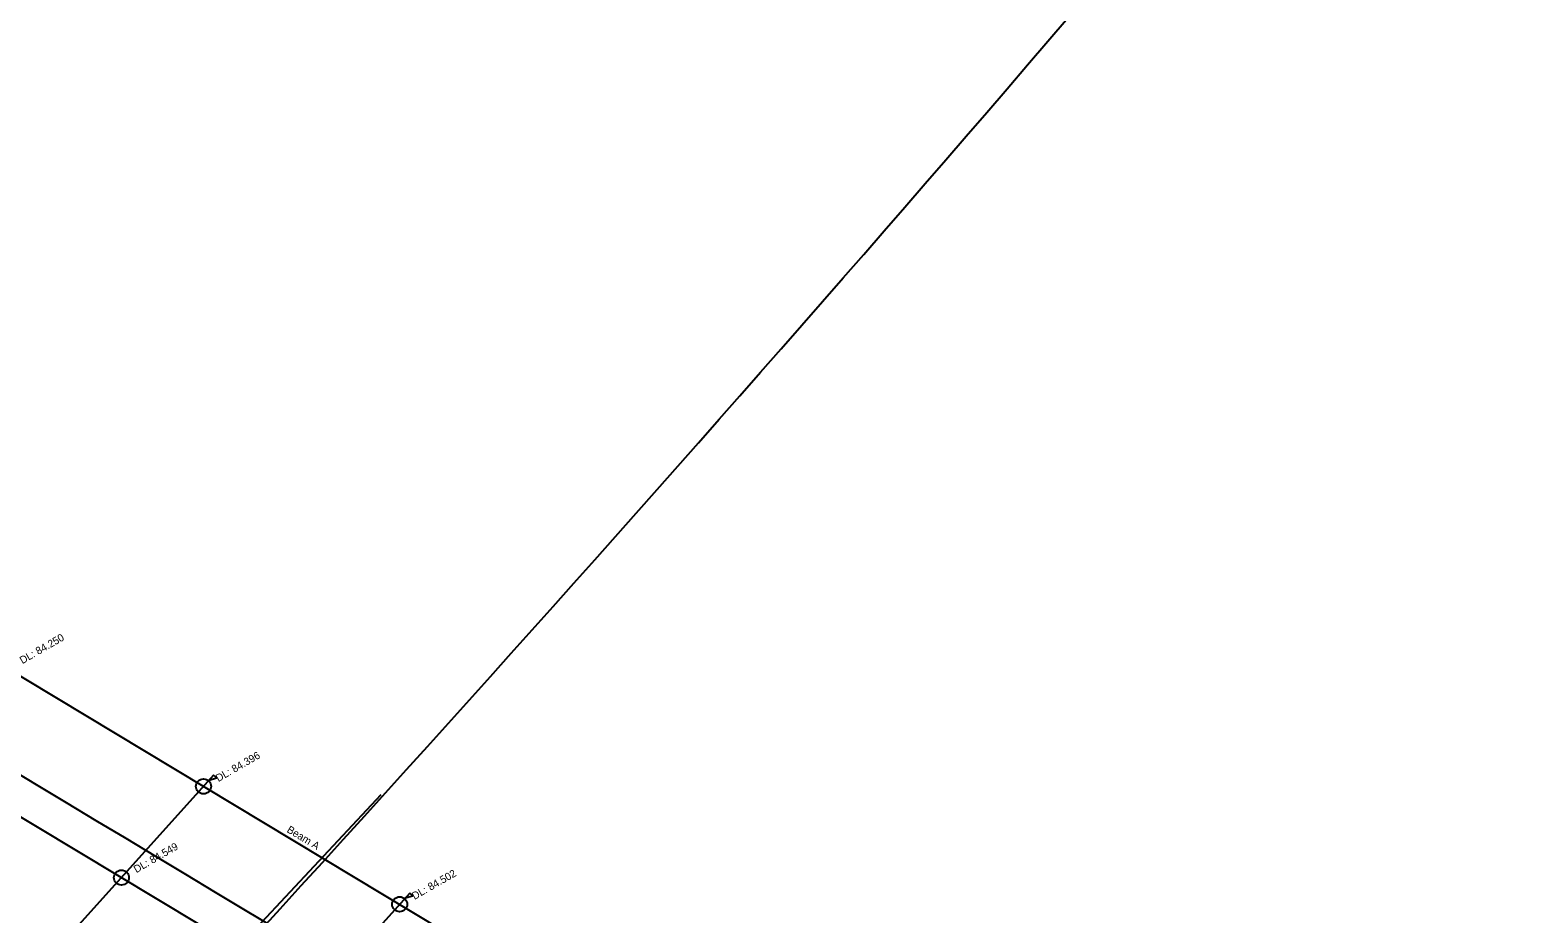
# Model space of a CAD drawing. Extents: x 3599070 to 3599898, y 342469 to 342989.
# Drawn here: x 3599620.3 to 3599720.4, y 342683.2 to 342741.9 of the extents above; entities that cross this region are included whole.
import ezdxf

# ---------------------------------------------------------------- set-up
doc = ezdxf.new("R2010")
doc.units = 0
for name, color, linetype in [('B', 7, 'Continuous'), ('EE', 7, 'Continuous'), ('GUARDRAIL', 7, 'Continuous'), ('PROLINE', 7, 'Continuous')]:
    doc.layers.add(name, color=color, linetype=linetype)

msp = doc.modelspace()

# ---------------------------------------------------------------- linework, layer by layer
at = {"layer": 'B'}
for p, q in [((3599565.51, 342731.51), (3599711.21, 342643.92)), ((3599560.06, 342725.46), (3599705.75, 342637.87))]:
    msp.add_line(p, q, dxfattribs=at)
at = {"layer": 'EE'}
for points in [[(3599632.45, 342692.41), (3599582.02, 342636.43)], [(3599632.16, 342692.09), (3599632.64, 342692.24), (3599632.45, 342692.41)], [(3599645.48, 342684.58), (3599595.05, 342628.6)], [(3599645.19, 342684.26), (3599645.66, 342684.41), (3599645.48, 342684.58)]]:
    msp.add_lwpolyline(points, dxfattribs=at)
for centre in [(3599631.78, 342691.67), (3599626.33, 342685.61), (3599644.81, 342683.84)]:
    msp.add_circle(centre, 0.499, dxfattribs=at)
at = {"layer": 'GUARDRAIL'}
for centre, radius, start, end in [((3597781.98, 344376.76), 2511.5, 317.27688, 323.34945), ((3597781.98, 344376.76), 2511.5, 317.27688, 323.34945), ((3597781.98, 344376.76), 2511.5, 317.27688, 323.34945), ((3597781.98, 344376.76), 2511.5, 317.27688, 323.34945), ((3597781.98, 344376.76), 2511.5, 317.27688, 323.34945), ((3597781.98, 344376.76), 2511.5, 317.27688, 323.34945), ((3597781.98, 344376.76), 2511.5, 317.27688, 323.34945), ((3597781.98, 344376.76), 2511.5, 317.27688, 323.34945), ((3597781.98, 344376.76), 2511.5, 317.27688, 323.34945), ((3597781.98, 344376.76), 2511.5, 317.27688, 323.34945), ((3594639.68, 334386.71), 9684.24, 58.937083, 60.687623), ((3594639.68, 334386.71), 9654.24, 58.937083, 60.687778)]:
    msp.add_arc(centre, radius, start, end, dxfattribs=at)
at = {"layer": 'PROLINE'}
msp.add_line((3599643.56, 342691.1), (3599574.7, 342617.56), dxfattribs=at)

# ---------------------------------------------------------------- texts
at = {"layer": 'B'}
msp.add_text('Beam A', height=0.499, rotation=328.986, dxfattribs=at).set_placement((3599637.27, 342688.66))
at = {"layer": 'EE'}
for s, p in [('DL: 84.250', (3599619.75, 342699.78)), ('DL: 84.396', (3599632.77, 342691.95)), ('DL: 84.549', (3599627.32, 342685.9)), ('DL: 84.502', (3599645.8, 342684.12))]:
    msp.add_text(s, height=0.499, rotation=30, dxfattribs=at).set_placement(p)

doc.saveas('drawing.dxf')
